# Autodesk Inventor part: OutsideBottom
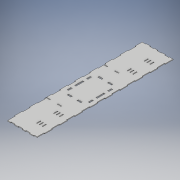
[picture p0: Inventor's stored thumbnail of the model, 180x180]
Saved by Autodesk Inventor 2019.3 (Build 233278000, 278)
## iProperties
Created: 2020-02
Part Number: OutsideBottom
Material: Generic
Document SubType Name: Modeling
Designer: KrystynWikoff
Density: 1 g/cm^3
Appearance: Default
Author: KrystynWikoff
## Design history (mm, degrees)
sketch "Sketch1"
  geometry: L1 (0, 0)-(101.6, 0); L2 (101.6, 0)-(101.6, -457.2); L3 (101.6, -457.2)-(0, -457.2); L4 (0, -457.2)-(0, 0)
  constraints: 8 end point, 2 parallel, 1 horizontal, 1 perpendicular
  dimensions: "d0" = 457.2 distance of L3.end L1.start; "d1" = 101.6 distance of L1.start L1.end
extrude "Extrusion1" new body sketch "Sketch1" distance "d2" = 2.3622; taper "d3" = 0 deg
sketch "Sketch2" dims "d11" = 25.4
  geometry: L1 (-101.6, 0)-(0, 0) reference; L2 (0, 0)-(-2.362, 0); L3 (-2.362, 0)-(-2.362, 25.4); L4 (-2.362, 25.4)-(0, 25.4); L5 (0, 25.4)-(0, 0); L6 (0, 50.8)-(-2.362, 50.8); L7 (-2.362, 50.8)-(-2.362, 76.2); L8 (-2.362, 76.2)-(0, 76.2); L9 (0, 76.2)-(0, 50.8); L10 (0, 101.6)-(-2.362, 101.6); L11 (-2.362, 101.6)-(-2.362, 127); L12 (-2.362, 127)-(0, 127); L13 (0, 127)-(0, 101.6); L14 (0, 152.4)-(-2.362, 152.4); L15 (-2.362, 152.4)-(-2.362, 177.8); L16 (-2.362, 177.8)-(0, 177.8); L17 (0, 177.8)-(0, 152.4); L18 (0, 203.2)-(-2.362, 203.2); L19 (-2.362, 203.2)-(-2.362, 228.6); L20 (-2.362, 228.6)-(0, 228.6); L21 (0, 228.6)-(0, 203.2); L22 (0, 254)-(-2.362, 254); L23 (-2.362, 254)-(-2.362, 279.4); L24 (-2.362, 279.4)-(0, 279.4); L25 (0, 279.4)-(0, 254); L26 (0, 304.8)-(-2.362, 304.8); L27 (-2.362, 304.8)-(-2.362, 330.2); L28 (-2.362, 330.2)-(0, 330.2); L29 (0, 330.2)-(0, 304.8); L30 (0, 355.6)-(-2.362, 355.6); L31 (-2.362, 355.6)-(-2.362, 381); L32 (-2.362, 381)-(0, 381); L33 (0, 381)-(0, 355.6); L34 (0, 406.4)-(-2.362, 406.4); L35 (-2.362, 406.4)-(-2.362, 431.8); L36 (-2.362, 431.8)-(0, 431.8); L37 (0, 431.8)-(0, 406.4)
  constraints: 72 end point, 2 parallel, 1 collinear, 1 horizontal, 1 perpendicular, 1 vertical, 63 other
  dimensions: "d4" = 25.4 distance of L2.end L3.end; "d5" = 2.3622 distance of L3.end L4.end; "d8" = 50.8 distance of L3.end L7.end
extrude "Extrusion2" cut sketch "Sketch2" distance "d13" = 2.3622; taper "d14" = 0 deg
sketch "Sketch3" dims "d22" = 25.4, "d32" = 25.4
  geometry: L1 (0, 0)-(-12.7, 0); L2 (-12.7, 0)-(-12.7, 2.362); L3 (-12.7, 2.362)-(0, 2.362); L4 (0, 2.362)-(0, 0); L5 (-25.4, 0)-(-38.1, 0); L6 (-38.1, 0)-(-38.1, 2.362); L7 (-38.1, 2.362)-(-25.4, 2.362); L8 (-25.4, 2.362)-(-25.4, 0); L9 (-50.8, 0)-(-63.5, 0); L10 (-63.5, 0)-(-63.5, 2.362); L11 (-63.5, 2.362)-(-50.8, 2.362); L12 (-50.8, 2.362)-(-50.8, 0); L13 (-76.2, 0)-(-88.9, 0); L14 (-88.9, 0)-(-88.9, 2.362); L15 (-88.9, 2.362)-(-76.2, 2.362); L16 (-76.2, 2.362)-(-76.2, 0); L17 (-101.6, 0)-(-114.3, 0); L18 (-114.3, 0)-(-114.3, 2.362); L19 (-114.3, 2.362)-(-101.6, 2.362); L20 (-101.6, 2.362)-(-101.6, 0); L21 (0, 457.2)-(-101.6, 457.2) reference; L22 (-12.7, 457.2)-(-25.4, 457.2); L23 (-25.4, 457.2)-(-25.4, 454.838); L24 (-25.4, 454.838)-(-12.7, 454.838); L25 (-12.7, 454.838)-(-12.7, 457.2); L26 (0, 431.8)-(0, 457.2) reference; L27 (-50.8, 457.2)-(-50.8, 454.838); L28 (-50.8, 454.838)-(-38.1, 454.838); L29 (-38.1, 457.2)-(-50.8, 457.2); L30 (-38.1, 454.838)-(-38.1, 457.2); L31 (-76.2, 457.2)-(-76.2, 454.838); L32 (-76.2, 454.838)-(-63.5, 454.838); L33 (-63.5, 457.2)-(-76.2, 457.2); L34 (-63.5, 454.838)-(-63.5, 457.2); L35 (-101.6, 457.2)-(-101.6, 454.838); L36 (-101.6, 454.838)-(-88.9, 454.838); L37 (-88.9, 457.2)-(-101.6, 457.2); L38 (-88.9, 454.838)-(-88.9, 457.2)
  constraints: 72 end point, 4 horizontal, 4 parallel, 2 perpendicular, 1 collinear, 1 point on line, 55 other
  dimensions: "d15" = 12.7 distance of L2.end L3.end; "d16" = 2.3622 distance of L1.end L2.end; "d19" = 25.4 distance of L2.end L6.end; "d24" = 12.7 distance of L23.end L24.end; "d25" = 12.7 distance between parallel lines of L26 L25; "d26" = 2.3622 distance of L24.end L22.start; "d29" = 25.4 distance of L23.end L27.end
extrude "Extrusion3" cut sketch "Sketch3" distance "d34" = 2.3622; taper "d35" = 0 deg
sketch "Sketch4"
  geometry: L1 (-101.6, -130.988)-(-88.9, -130.988); L2 (-88.9, -130.988)-(-88.9, -133.35); L3 (-88.9, -133.35)-(-101.6, -133.35); L4 (-101.6, -133.35)-(-101.6, -130.988); L5 (-88.9, 0)-(-101.6, 0) reference; L6 (-101.6, -130.988)-(-50.8, -130.988); L7 (-50.8, -130.988)-(-63.5, -130.988); L8 (-63.5, -130.988)-(-63.5, -133.35); L9 (-63.5, -133.35)-(-50.8, -133.35); L10 (-50.8, -133.35)-(-50.8, -130.988); L11 (-101.6, -323.85)-(-88.9, -323.85); L12 (-88.9, -323.85)-(-88.9, -326.212); L13 (-88.9, -326.212)-(-101.6, -326.212); L14 (-101.6, -326.212)-(-101.6, -323.85); L15 (-101.6, -457.2)-(0, -457.2) reference; L16 (-101.6, -323.85)-(-50.8, -323.85); L17 (-50.8, -323.85)-(-63.5, -323.85); L18 (-63.5, -323.85)-(-63.5, -326.212); L19 (-63.5, -326.212)-(-50.8, -326.212); L20 (-50.8, -326.212)-(-50.8, -323.85); 3 further points; 1 other entity
  constraints: 36 end point, 9 parallel, 5 horizontal, 4 perpendicular, 1 other
  dimensions: "d36" = 130.9878 distance between parallel lines of L1 L5; "d37" = 2.3622 distance of L1.end L2.end; "d38" = 12.7 distance of L1.start L1.end; "d39" = 50.8 distance of L1.start L6.end; "d40" = 12.7 distance of L8.end L9.end; "d41" = 2.3622 distance of L7.end L8.end; "d43" = 2.3622 distance of L11.end L12.end; "d44" = 12.7 distance of L11.start L11.end; "d45" = 50.8 distance of L11.start L16.end; "d46" = 12.7 distance of L18.end L19.end; "d47" = 2.3622 distance of L17.end L18.end; "d82" = 130.9878 distance between parallel lines of L15 L13; "d83" = 0 horizontal extent of L14; "d84" = 0 horizontal extent of L4
extrude "Extrusion4" cut sketch "Sketch4" distance "d48" = 25.4; taper "d49" = 0 deg
sketch "Sketch5"
  geometry: L1 (-12.7, 0)-(-25.4, 0) reference; L2 (-22.362, -111.2)-(-22.362, -41.2); L3 (-2.362, -76.2)-(-2.362, -50.8) reference; L4 (0, -76.2)-(-2.362, -76.2) reference; L5 (-22.362, -41.2)-(-24.724, -41.2); L6 (-24.724, -41.2)-(-24.724, -53.9); L7 (-24.724, -53.9)-(-22.362, -53.9); L8 (-22.362, -53.9)-(-22.362, -41.2); L9 (-22.362, -111.2)-(-24.724, -111.2); L10 (-24.724, -111.2)-(-24.724, -98.5); L11 (-24.724, -98.5)-(-22.362, -98.5); L12 (-22.362, -98.5)-(-22.362, -111.2); L13 (-22.362, -346)-(-22.362, -416); L14 (-2.362, -381)-(-2.362, -355.6) reference; L15 (0, -381)-(-2.362, -381) reference; L16 (-22.362, -346)-(-24.724, -346); L17 (-24.724, -346)-(-24.724, -358.7); L18 (-24.724, -358.7)-(-22.362, -358.7); L19 (-22.362, -358.7)-(-22.362, -346); L20 (-22.362, -416)-(-24.724, -416); L21 (-24.724, -416)-(-24.724, -403.3); L22 (-24.724, -403.3)-(-22.362, -403.3); L23 (-22.362, -403.3)-(-22.362, -416); L24 (-22.362, -346)-(-32.362, -346); L25 (-32.362, -346)-(-34.724, -346); L26 (-34.724, -346)-(-34.724, -358.7); L27 (-34.724, -358.7)-(-32.362, -358.7); L28 (-32.362, -358.7)-(-32.362, -346); L29 (-22.362, -416)-(-32.362, -416); L30 (-32.362, -416)-(-34.724, -416); L31 (-34.724, -416)-(-34.724, -403.3); L32 (-34.724, -403.3)-(-32.362, -403.3); L33 (-32.362, -403.3)-(-32.362, -416); L34 (-22.362, -41.2)-(-32.362, -41.2); L35 (-32.362, -41.2)-(-34.724, -41.2); L36 (-34.724, -41.2)-(-34.724, -53.9); L37 (-34.724, -53.9)-(-32.362, -53.9); L38 (-32.362, -53.9)-(-32.362, -41.2); L39 (-22.362, -111.2)-(-32.362, -111.2); L40 (-32.362, -111.2)-(-34.724, -111.2); L41 (-34.724, -111.2)-(-34.724, -98.5); L42 (-34.724, -98.5)-(-32.362, -98.5); L43 (-32.362, -98.5)-(-32.362, -111.2); L44 (-41, -346)-(-43.362, -346); L45 (-43.362, -346)-(-43.362, -358.7); L46 (-43.362, -358.7)-(-41, -358.7); L47 (-41, -358.7)-(-41, -346); L48 (0, -355.6)-(0, -330.2) reference; L49 (-41, -346)-(-34.724, -346); L50 (-43.362, -416)-(-41, -416); L51 (-41, -416)-(-41, -403.3); L52 (-41, -403.3)-(-43.362, -403.3); L53 (-43.362, -403.3)-(-43.362, -416); L54 (-41, -416)-(-34.724, -416); L55 (0, -406.4)-(0, -381) reference; L56 (-43.362, -111.2)-(-41, -111.2); L57 (-41, -111.2)-(-41, -98.5); L58 (-41, -98.5)-(-43.362, -98.5); L59 (-43.362, -98.5)-(-43.362, -111.2); L60 (-43.362, -53.9)-(-41, -53.9); L61 (-41, -53.9)-(-41, -41.2); L62 (-41, -41.2)-(-43.362, -41.2); L63 (-43.362, -41.2)-(-43.362, -53.9); L64 (0, -101.6)-(0, -76.2) reference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; 1 further point
  constraints: 116 end point, 25 parallel, 19 horizontal, 12 perpendicular, 2 point on line
  dimensions: "d53" = 70 distance of L2.start L2.end; "d54" = 20 distance between parallel lines of L3 L2; "d56" = 35 distance from line of L2.end L4; "d57" = 12.7 distance of L5.end L6.end; "d58" = 2.3622 distance of L6.end L7.end; "d59" = 2.3622 distance of L2.start L9.end; "d60" = 12.7 distance of L9.end L10.end; "d61" = 20 distance between parallel lines of L13 L14; "d62" = 70 distance of L13.start L13.end; "d63" = 35 distance from line of L15 L13.start; "d64" = 2.3622 distance of L17.end L18.end; "d65" = 12.7 distance of L16.end L17.end; "d66" = 12.7 distance of L20.end L21.end; "d67" = 2.3622 distance of L21.end L22.end; "d68" = 10 distance of L13.start L24.end; "d69" = 2.3622 distance of L26.end L27.end; "d70" = 12.7 distance of L25.end L26.end; "d71" = 12.7 distance of L32.end L29.end; "d72" = 2.3622 distance of L31.end L32.end; "d73" = 10 distance of L13.end L29.end; "d74" = 10 distance of L2.end L34.end; "d75" = 12.7 distance of L37.end L34.end; "d76" = 2.3622 distance of L34.end L35.end; "d77" = 12.7 distance of L42.end L39.end; "d78" = 2.3622 distance of L41.end L42.end; "d79" = 10 distance of L2.start L39.end; "d97" = 12.7 distance of L44.end L45.end; "d98" = 2.3622 distance of L45.end L46.end; "d99" = 41 distance between parallel lines of L48 L47; "d100" = 12.7 distance of L52.end L50.start; "d101" = 2.3622 distance of L50.start L50.end; "d102" = 41 distance between parallel lines of L55 L51; "d103" = 12.7 distance of L58.end L56.start; "d104" = 2.3622 distance of L56.start L56.end; "d105" = 12.7 distance of L62.end L60.start; "d107" = 41 distance between parallel lines of L64 L57
extrude "Extrusion5" cut sketch "Sketch5" distance "d80" = 25.4; taper "d81" = 0 deg
sketch "Sketch6" dims "d93" = 25.4
  geometry: L1 (-101.6, 326.212)-(-101.6, 454.838) reference; L2 (-101.6, 431.8)-(-99.238, 431.8); L3 (-99.238, 431.8)-(-99.238, 406.4); L4 (-99.238, 406.4)-(-101.6, 406.4); L5 (-101.6, 406.4)-(-101.6, 431.8); L6 (-76.2, 457.2)-(-88.9, 457.2) reference; L7 (-101.6, 381)-(-99.238, 381); L8 (-99.238, 381)-(-99.238, 355.6); L9 (-99.238, 355.6)-(-101.6, 355.6); L10 (-101.6, 355.6)-(-101.6, 381); L11 (-101.6, 330.2)-(-99.238, 330.2); L12 (-99.238, 330.2)-(-99.238, 304.8); L13 (-99.238, 304.8)-(-101.6, 304.8); L14 (-101.6, 304.8)-(-101.6, 330.2); L15 (-101.6, 279.4)-(-99.238, 279.4); L16 (-99.238, 279.4)-(-99.238, 254); L17 (-99.238, 254)-(-101.6, 254); L18 (-101.6, 254)-(-101.6, 279.4); L19 (-101.6, 228.6)-(-99.238, 228.6); L20 (-99.238, 228.6)-(-99.238, 203.2); L21 (-99.238, 203.2)-(-101.6, 203.2); L22 (-101.6, 203.2)-(-101.6, 228.6); L23 (-101.6, 177.8)-(-99.238, 177.8); L24 (-99.238, 177.8)-(-99.238, 152.4); L25 (-99.238, 152.4)-(-101.6, 152.4); L26 (-101.6, 152.4)-(-101.6, 177.8); L27 (-101.6, 127)-(-99.238, 127); L28 (-99.238, 127)-(-99.238, 101.6); L29 (-99.238, 101.6)-(-101.6, 101.6); L30 (-101.6, 101.6)-(-101.6, 127); L31 (-101.6, 76.2)-(-99.238, 76.2); L32 (-99.238, 76.2)-(-99.238, 50.8); L33 (-99.238, 50.8)-(-101.6, 50.8); L34 (-101.6, 50.8)-(-101.6, 76.2); L35 (-101.6, 25.4)-(-99.238, 25.4); L36 (-99.238, 25.4)-(-99.238, 0); L37 (-99.238, 0)-(-101.6, 0); L38 (-101.6, 0)-(-101.6, 25.4); 1 further point
  constraints: 72 end point, 2 parallel, 1 horizontal, 1 perpendicular, 1 point on line, 1 vertical, 64 other
  dimensions: "d85" = 25.4 distance between parallel lines of L6 L2; "d86" = 25.4 distance of L2.end L3.end; "d87" = 2.3622 distance of L3.end L4.end; "d90" = 50.8 distance of L2.start L7.start
extrude "Extrusion6" cut sketch "Sketch6" distance "d95" = 25.4; taper "d96" = 0 deg
sketch "Sketch7"
  geometry: L1 (-13.076, 282.499)-(-88.9, 282.499); L2 (-88.9, 282.499)-(-88.9, 174.674); L3 (-88.9, 174.674)-(-13.076, 174.674); L4 (-13.076, 174.674)-(-13.076, 282.499); L5 (-101.6, 254)-(-101.6, 228.6) reference; L6 (-50.8, 323.85)-(-63.5, 323.85) reference; L7 (-13.076, 267.437)-(-17.8, 267.437); L8 (-17.8, 267.437)-(-17.8, 254.737); L9 (-17.8, 254.737)-(-13.076, 254.737); L10 (-13.076, 254.737)-(-13.076, 267.437); L11 (-13.076, 189.737)-(-17.8, 189.737); L12 (-17.8, 189.737)-(-17.8, 202.437); L13 (-17.8, 202.437)-(-13.076, 202.437); L14 (-13.076, 202.437)-(-13.076, 189.737); L15 (-13.076, 242.037)-(-17.8, 242.037); L16 (-17.8, 242.037)-(-17.8, 215.137); L17 (-17.8, 215.137)-(-13.076, 215.137); L18 (-13.076, 215.137)-(-13.076, 242.037); L19 (-88.9, 267.437)-(-84.176, 267.437); L20 (-84.176, 267.437)-(-84.176, 254.737); L21 (-84.176, 254.737)-(-88.9, 254.737); L22 (-88.9, 254.737)-(-88.9, 267.437); L23 (-88.9, 242.037)-(-84.176, 242.037); L24 (-84.176, 242.037)-(-84.176, 215.137); L25 (-84.176, 215.137)-(-88.9, 215.137); L26 (-88.9, 215.137)-(-88.9, 242.037); L27 (-88.9, 202.437)-(-84.176, 202.437); L28 (-84.176, 202.437)-(-84.176, 189.737); L29 (-84.176, 189.737)-(-88.9, 189.737); L30 (-88.9, 189.737)-(-88.9, 202.437); L31 (-28.138, 282.499)-(-40.838, 282.499); L32 (-40.838, 282.499)-(-40.838, 277.774); L33 (-40.838, 277.774)-(-28.138, 277.774); L34 (-28.138, 277.774)-(-28.138, 282.499); L35 (-73.838, 282.499)-(-61.138, 282.499); L36 (-61.138, 282.499)-(-61.138, 277.774); L37 (-61.138, 277.774)-(-73.838, 277.774); L38 (-73.838, 277.774)-(-73.838, 282.499); L39 (-28.138, 174.674)-(-40.838, 174.674); L40 (-40.838, 174.674)-(-40.838, 179.399); L41 (-40.838, 179.399)-(-28.138, 179.399); L42 (-28.138, 179.399)-(-28.138, 174.674); L43 (-61.138, 174.674)-(-73.838, 174.674); L44 (-73.838, 174.674)-(-73.838, 179.399); L45 (-73.838, 179.399)-(-61.138, 179.399); L46 (-61.138, 179.399)-(-61.138, 174.674); 1 further point
  constraints: 88 end point, 22 parallel, 11 horizontal, 11 perpendicular, 10 point on line
  dimensions: "d108" = 12.7 distance between parallel lines of L5 L2; "d109" = 41.3512 distance between parallel lines of L6 L1; "d110" = 107.8244 distance of L3.end L1.start; "d111" = 75.8244 distance of L2.end L3.end; "d112" = 15.0622 distance between parallel lines of L1 L7; "d113" = 12.7 distance of L7.end L8.end; "d114" = 4.7244 distance of L7.start L7.end; "d115" = 4.7244 distance of L12.end L13.end; "d116" = 12.7 distance of L11.end L12.end; "d117" = 15.0622 distance between parallel lines of L3 L11; "d118" = 4.7244 distance of L15.start L15.end; "d119" = 12.7 distance between parallel lines of L9 L15; "d120" = 12.7 distance between parallel lines of L13 L17; "d121" = 12.7 distance of L19.end L20.end; "d122" = 15.0622 distance between parallel lines of L1 L19; "d123" = 4.7244 distance of L19.start L19.end; "d124" = 12.7 distance between parallel lines of L21 L23; "d125" = 4.7244 distance of L24.end L25.end; "d126" = 15.0622 distance between parallel lines of L3 L29; "d127" = 12.7 distance of L27.end L28.end; "d128" = 4.7244 distance of L28.end L29.end; "d129" = 12.7 distance between parallel lines of L25 L27; "d130" = 12.7 distance of L32.end L33.end; "d131" = 15.0622 distance between parallel lines of L4 L34; "d132" = 4.7244 distance of L33.end L31.start; "d133" = 15.0622 distance between parallel lines of L2 L38; "d134" = 12.7 distance of L36.end L37.end; "d135" = 4.7244 distance of L35.end L36.end; "d136" = 15.0622 distance between parallel lines of L4 L42; "d137" = 12.7 distance of L40.end L41.end; "d138" = 4.7244 distance of L41.end L39.start; "d139" = 15.0622 distance between parallel lines of L2 L44; "d140" = 12.7 distance of L44.end L45.end; "d141" = 4.7244 distance of L45.end L43.start
extrude "Extrusion7" cut sketch "Sketch7" distance "d142" = 25.4; taper "d143" = 0 deg
body "Solid1"
